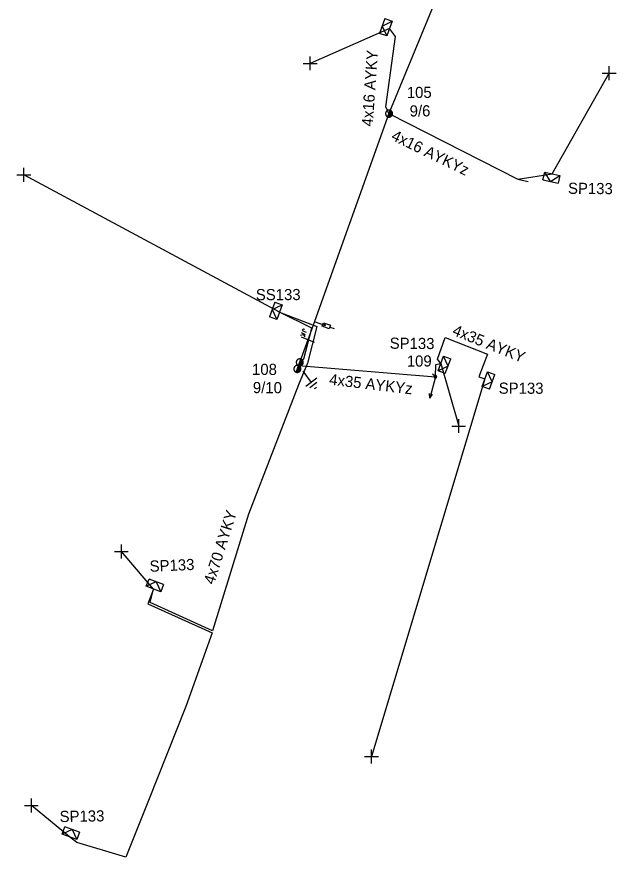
# Model space of a CAD drawing. Extents: x -748492 to -735633, y -1146251 to -1139940.
# Drawn here: x -740373.9 to -740320.2, y -1142310.5 to -1142235.2 of the extents above; entities that cross this region are included whole.
import ezdxf

# ---------------------------------------------------------------- set-up
doc = ezdxf.new("R2010")
doc.units = 0
for name, color, linetype in [('Vrstva 1', 7, 'Continuous'), ('Vrstva 12', 7, 'Continuous'), ('Vrstva 13', 7, 'Continuous'), ('Vrstva 14', 7, 'Continuous'), ('Vrstva 15', 7, 'Continuous'), ('Vrstva 16', 7, 'Continuous'), ('Vrstva 18', 7, 'Continuous'), ('Vrstva 2', 7, 'Continuous'), ('Vrstva 31', 7, 'Continuous'), ('Vrstva 33', 7, 'Continuous'), ('Vrstva 34', 7, 'Continuous'), ('Vrstva 5', 7, 'Continuous'), ('Vrstva 52', 7, 'Continuous'), ('Vrstva 53', 7, 'Continuous'), ('Vrstva 54', 7, 'Continuous'), ('Vrstva 55', 7, 'Continuous'), ('Vrstva 59', 7, 'Continuous'), ('Vrstva 6', 7, 'Continuous'), ('Vrstva 9', 7, 'Continuous')]:
    doc.layers.add(name, color=color, linetype=linetype)

# ---------------------------------------------------------------- blocks, each defined once
blk = doc.blocks.new('NN440')
at = {"layer": 'Vrstva 2'}
for points in [[(0.63, 0), (0.63, 0.06), (0.62, 0.13), (0.6, 0.19), (0.58, 0.25), (0.55, 0.31), (0.51, 0.37), (0.47, 0.42), (0.42, 0.46), (0.37, 0.51), (0.32, 0.54), (0.26, 0.57), (0.2, 0.59), (0.13, 0.61), (0.07, 0.62), (0, 0.63), (-0.06, 0.62), (-0.13, 0.61), (-0.19, 0.59), (-0.26, 0.57), (-0.31, 0.54), (-0.37, 0.51), (-0.42, 0.46), (-0.47, 0.42), (-0.51, 0.37), (-0.54, 0.31), (-0.57, 0.25), (-0.6, 0.19), (-0.62, 0.13), (-0.63, 0.06), (-0.63, 0), (-0.63, -0.07), (-0.62, -0.14), (-0.6, -0.2), (-0.57, -0.26), (-0.54, -0.32), (-0.51, -0.37), (-0.47, -0.43), (-0.42, -0.47), (-0.37, -0.51), (-0.31, -0.55), (-0.26, -0.58), (-0.19, -0.6), (-0.13, -0.62), (-0.06, -0.63), (0, -0.63), (0.07, -0.63), (0.13, -0.62), (0.2, -0.6), (0.26, -0.58), (0.32, -0.55), (0.37, -0.51), (0.42, -0.47), (0.47, -0.43), (0.51, -0.37), (0.55, -0.32), (0.58, -0.26), (0.6, -0.2), (0.62, -0.14), (0.63, -0.07), (0.63, 0)], [(-0.63, 0), (0.63, 0)], [(-0.6, -0.18), (0.57, -0.18)], [(-0.51, -0.32), (0.5, -0.32)], [(-0.37, -0.47), (0.35, -0.47)]]:
    blk.add_lwpolyline(points, dxfattribs=at)
blk = doc.blocks.new('NN450')
at = {"layer": 'Vrstva 2'}
for points in [[(0, 0), (0, 0.07), (-0.01, 0.13), (-0.03, 0.19), (-0.05, 0.25), (-0.08, 0.31), (-0.12, 0.37), (-0.16, 0.42), (-0.21, 0.46), (-0.26, 0.51), (-0.31, 0.54), (-0.37, 0.57), (-0.43, 0.59), (-0.5, 0.61), (-0.56, 0.62), (-0.63, 0.62), (-0.69, 0.62), (-0.75, 0.61), (-0.82, 0.59), (-0.88, 0.57), (-0.94, 0.54), (-0.99, 0.51), (-1.04, 0.46), (-1.09, 0.42), (-1.13, 0.37), (-1.17, 0.31), (-1.2, 0.25), (-1.22, 0.19), (-1.24, 0.13), (-1.25, 0.07), (-1.25, 0), (-1.25, -0.07), (-1.24, -0.13), (-1.22, -0.19), (-1.2, -0.25), (-1.17, -0.31), (-1.13, -0.37), (-1.09, -0.42), (-1.04, -0.46), (-0.99, -0.51), (-0.94, -0.54), (-0.88, -0.57), (-0.82, -0.59), (-0.75, -0.61), (-0.69, -0.62), (-0.62, -0.63), (-0.56, -0.62), (-0.5, -0.61), (-0.43, -0.59), (-0.37, -0.57), (-0.31, -0.54), (-0.26, -0.51), (-0.21, -0.46), (-0.16, -0.42), (-0.12, -0.37), (-0.08, -0.31), (-0.05, -0.25), (-0.03, -0.19), (-0.01, -0.13), (0, -0.07), (0, 0)], [(1.25, 0), (1.25, 0.07), (1.24, 0.13), (1.22, 0.19), (1.2, 0.25), (1.17, 0.31), (1.13, 0.37), (1.09, 0.42), (1.04, 0.46), (0.99, 0.51), (0.94, 0.54), (0.88, 0.57), (0.82, 0.59), (0.75, 0.61), (0.69, 0.62), (0.62, 0.62), (0.56, 0.62), (0.5, 0.61), (0.43, 0.59), (0.37, 0.57), (0.31, 0.54), (0.26, 0.51), (0.21, 0.46), (0.16, 0.42), (0.12, 0.37), (0.08, 0.31), (0.05, 0.25), (0.03, 0.19), (0.01, 0.13), (0, 0.07), (0, 0), (0, -0.07), (0.01, -0.13), (0.03, -0.19), (0.05, -0.25), (0.08, -0.31), (0.12, -0.37), (0.16, -0.42), (0.21, -0.46), (0.26, -0.51), (0.31, -0.54), (0.37, -0.57), (0.43, -0.59), (0.5, -0.61), (0.56, -0.62), (0.63, -0.63), (0.69, -0.62), (0.75, -0.61), (0.82, -0.59), (0.88, -0.57), (0.94, -0.54), (0.99, -0.51), (1.04, -0.46), (1.09, -0.42), (1.13, -0.37), (1.17, -0.31), (1.2, -0.25), (1.22, -0.19), (1.24, -0.13), (1.25, -0.07), (1.25, 0)], [(-1.25, 0), (1.25, 0)], [(-1.23, -0.16), (-0.02, -0.16)], [(-1.16, -0.32), (-0.09, -0.32)], [(-1.03, -0.47), (-0.22, -0.47)], [(0.02, -0.16), (1.23, -0.16)], [(0.09, -0.32), (1.16, -0.32)], [(0.22, -0.47), (1.03, -0.47)]]:
    blk.add_lwpolyline(points, dxfattribs=at)
blk = doc.blocks.new('NN560')
at = {"layer": 'Vrstva 2'}
for points in [[(1.999, -0.001), (1.59, 0.141)], [(0, -0.001), (1.999, -0.001)], [(1.999, -0.001), (1.59, -0.134)]]:
    blk.add_lwpolyline(points, dxfattribs=at)
blk = doc.blocks.new('NN840')
at = {"layer": 'Vrstva 15'}
for points in [[(0.003, 0.619), (0.003, -0.631)], [(-0.745, -0.71), (-0.745, -0.66)], [(-0.73, -0.764), (-0.745, -0.71)], [(-0.538, -0.71), (-0.558, -0.764)], [(-0.538, -0.385), (-0.538, -0.71)], [(-0.332, -0.385), (-0.332, -0.798)], [(-0.332, -0.641), (-0.125, -0.385)], [(-0.263, -0.557), (-0.091, -0.798)], [(-0.657, -0.798), (-0.73, -0.764)], [(-0.627, -0.798), (-0.657, -0.798)], [(-0.558, -0.764), (-0.627, -0.798)]]:
    blk.add_lwpolyline(points, dxfattribs=at)
blk = doc.blocks.new('NN800')
at = {"layer": 'Vrstva 1'}
for points in [[(-0.442, 0.442), (0.442, -0.442)], [(-0.442, -0.442), (0.442, 0.442)]]:
    blk.add_lwpolyline(points, dxfattribs=at)
blk = doc.blocks.new('NN820')
at = {"layer": 'Vrstva 13'}
for points in [[(-0.003, 0.004), (-0.003, -1.049)], [(-0.165, -0.813), (0.165, -0.813)], [(-0.165, -1.473), (-0.165, -0.813)], [(0.165, -1.473), (-0.165, -1.473)], [(-0.003, -1.049), (-0.062, -0.926)], [(-0.003, -1.049), (0.057, -0.926)], [(-0.003, -1.473), (-0.003, -1.871)], [(0.165, -0.813), (0.165, -1.473)]]:
    blk.add_lwpolyline(points, dxfattribs=at)
blk = doc.blocks.new('NN630')
at = {"layer": 'Vrstva 9'}
for points in [[(-0.003, -0.7), (-0.703, 0)], [(-0.703, -0.7), (-0.703, 0), (0.697, 0), (0.697, -0.7)], [(-0.703, -0.7), (0.697, -0.7)], [(-0.003, -0.7), (0.697, 0)]]:
    blk.add_lwpolyline(points, dxfattribs=at)
blk = doc.blocks.new('NN810')
at = {"layer": 'Vrstva 14'}
for points in [[(0.004, -0.64), (0.004, -1.89)], [(0.629, -1.89), (-0.621, -1.89)], [(0.388, -2.2), (-0.399, -2.2)], [(0.004, -2.515), (-0.124, -2.515)], [(0.137, -2.515), (0.004, -2.515)]]:
    blk.add_lwpolyline(points, dxfattribs=at)
blk = doc.blocks.new('NN500')
at = {"layer": 'Vrstva 2'}
for points in [[(0, -0.24), (0.02, -0.23), (0.05, -0.23), (0.07, -0.22), (0.09, -0.22), (0.12, -0.2), (0.14, -0.19), (0.16, -0.18), (0.17, -0.16), (0.19, -0.14), (0.2, -0.12), (0.21, -0.1), (0.22, -0.07), (0.23, -0.05), (0.23, -0.02), (0.23, 0), (0.23, 0.02), (0.23, 0.05), (0.22, 0.07), (0.21, 0.1), (0.2, 0.12), (0.19, 0.14), (0.17, 0.16), (0.16, 0.17), (0.14, 0.19), (0.12, 0.2), (0.09, 0.21), (0.07, 0.22), (0.05, 0.23), (0.02, 0.23), (0, 0.23), (-0.03, 0.23), (-0.05, 0.23), (-0.07, 0.22), (-0.1, 0.21), (-0.12, 0.2), (-0.14, 0.19), (-0.16, 0.17), (-0.18, 0.16), (-0.19, 0.14), (-0.2, 0.12), (-0.22, 0.1), (-0.22, 0.07), (-0.23, 0.05), (-0.23, 0.02), (-0.24, 0), (-0.23, -0.02), (-0.23, -0.05), (-0.22, -0.07), (-0.22, -0.1), (-0.2, -0.12), (-0.19, -0.14), (-0.18, -0.16), (-0.16, -0.18), (-0.14, -0.19), (-0.12, -0.2), (-0.1, -0.22), (-0.07, -0.22), (-0.05, -0.23), (-0.03, -0.23), (0, -0.24)], [(0, -0.24), (0.02, -0.23), (0.05, -0.23), (0.07, -0.22), (0.09, -0.22), (0.12, -0.2), (0.14, -0.19), (0.16, -0.18), (0.17, -0.16), (0.19, -0.14), (0.2, -0.12), (0.21, -0.1), (0.22, -0.07), (0.23, -0.05), (0.23, -0.02), (0.23, 0), (0.23, 0.02), (0.23, 0.05), (0.22, 0.07), (0.21, 0.1), (0.2, 0.12), (0.19, 0.14), (0.17, 0.16), (0.16, 0.17), (0.14, 0.19), (0.12, 0.2), (0.09, 0.21), (0.07, 0.22), (0.05, 0.23), (0.02, 0.23), (0, 0.23), (-0.03, 0.23), (-0.05, 0.23), (-0.07, 0.22), (-0.1, 0.21), (-0.12, 0.2), (-0.14, 0.19), (-0.16, 0.17), (-0.18, 0.16), (-0.19, 0.14), (-0.2, 0.12), (-0.22, 0.1), (-0.22, 0.07), (-0.23, 0.05), (-0.23, 0.02), (-0.24, 0), (-0.23, -0.02), (-0.23, -0.05), (-0.22, -0.07), (-0.22, -0.1), (-0.2, -0.12), (-0.19, -0.14), (-0.18, -0.16), (-0.16, -0.18), (-0.14, -0.19), (-0.12, -0.2), (-0.1, -0.22), (-0.07, -0.22), (-0.05, -0.23), (-0.03, -0.23), (0, -0.24)], [(0, -0.21), (0.02, -0.2), (0.04, -0.2), (0.06, -0.2), (0.08, -0.19), (0.1, -0.18), (0.12, -0.17), (0.14, -0.15), (0.15, -0.14), (0.16, -0.12), (0.18, -0.1), (0.19, -0.08), (0.19, -0.06), (0.2, -0.04), (0.2, -0.02), (0.2, 0), (0.2, 0.02), (0.2, 0.04), (0.19, 0.06), (0.19, 0.08), (0.18, 0.1), (0.16, 0.12), (0.15, 0.14), (0.14, 0.15), (0.12, 0.17), (0.1, 0.18), (0.08, 0.19), (0.06, 0.19), (0.04, 0.2), (0.02, 0.2), (0, 0.2), (-0.02, 0.2), (-0.04, 0.2), (-0.06, 0.19), (-0.08, 0.19), (-0.1, 0.18), (-0.12, 0.17), (-0.14, 0.15), (-0.15, 0.14), (-0.17, 0.12), (-0.18, 0.1), (-0.19, 0.08), (-0.2, 0.06), (-0.2, 0.04), (-0.21, 0.02), (-0.21, 0), (-0.21, -0.02), (-0.2, -0.04), (-0.2, -0.06), (-0.19, -0.08), (-0.18, -0.1), (-0.17, -0.12), (-0.15, -0.14), (-0.14, -0.15), (-0.12, -0.17), (-0.1, -0.18), (-0.08, -0.19), (-0.06, -0.2), (-0.04, -0.2), (-0.02, -0.2), (0, -0.21)], [(0, -0.18), (0.02, -0.18), (0.04, -0.17), (0.05, -0.17), (0.07, -0.16), (0.09, -0.15), (0.1, -0.14), (0.12, -0.13), (0.13, -0.12), (0.14, -0.1), (0.15, -0.09), (0.16, -0.07), (0.17, -0.05), (0.17, -0.04), (0.17, -0.02), (0.17, 0), (0.17, 0.02), (0.17, 0.04), (0.17, 0.05), (0.16, 0.07), (0.15, 0.09), (0.14, 0.1), (0.13, 0.12), (0.12, 0.13), (0.1, 0.14), (0.09, 0.15), (0.07, 0.16), (0.05, 0.17), (0.04, 0.17), (0.02, 0.17), (0, 0.18), (-0.02, 0.17), (-0.04, 0.17), (-0.06, 0.17), (-0.07, 0.16), (-0.09, 0.15), (-0.1, 0.14), (-0.12, 0.13), (-0.13, 0.12), (-0.14, 0.1), (-0.15, 0.09), (-0.16, 0.07), (-0.17, 0.05), (-0.17, 0.04), (-0.18, 0.02), (-0.18, 0), (-0.18, -0.02), (-0.17, -0.04), (-0.17, -0.05), (-0.16, -0.07), (-0.15, -0.09), (-0.14, -0.1), (-0.13, -0.12), (-0.12, -0.13), (-0.1, -0.14), (-0.09, -0.15), (-0.07, -0.16), (-0.06, -0.17), (-0.04, -0.17), (-0.02, -0.18), (0, -0.18)], [(0, -0.15), (0.01, -0.15), (0.03, -0.14), (0.04, -0.14), (0.06, -0.13), (0.07, -0.13), (0.08, -0.12), (0.1, -0.11), (0.11, -0.1), (0.12, -0.09), (0.13, -0.07), (0.13, -0.06), (0.14, -0.05), (0.14, -0.03), (0.14, -0.02), (0.14, 0), (0.14, 0.01), (0.14, 0.03), (0.14, 0.04), (0.13, 0.06), (0.13, 0.07), (0.12, 0.09), (0.11, 0.1), (0.1, 0.11), (0.08, 0.12), (0.07, 0.13), (0.06, 0.13), (0.04, 0.14), (0.03, 0.14), (0.01, 0.14), (0, 0.15), (-0.02, 0.14), (-0.03, 0.14), (-0.05, 0.14), (-0.06, 0.13), (-0.07, 0.13), (-0.09, 0.12), (-0.1, 0.11), (-0.11, 0.1), (-0.12, 0.09), (-0.13, 0.07), (-0.13, 0.06), (-0.14, 0.04), (-0.14, 0.03), (-0.15, 0.01), (-0.15, 0), (-0.15, -0.02), (-0.14, -0.03), (-0.14, -0.05), (-0.13, -0.06), (-0.13, -0.07), (-0.12, -0.09), (-0.11, -0.1), (-0.1, -0.11), (-0.09, -0.12), (-0.07, -0.13), (-0.06, -0.13), (-0.05, -0.14), (-0.03, -0.14), (-0.02, -0.15), (0, -0.15)], [(0, -0.12), (0.01, -0.12), (0.02, -0.11), (0.03, -0.11), (0.05, -0.11), (0.06, -0.1), (0.07, -0.09), (0.08, -0.09), (0.09, -0.08), (0.09, -0.07), (0.1, -0.06), (0.11, -0.05), (0.11, -0.04), (0.11, -0.02), (0.11, -0.01), (0.12, 0), (0.11, 0.01), (0.11, 0.02), (0.11, 0.04), (0.11, 0.05), (0.1, 0.06), (0.09, 0.07), (0.09, 0.08), (0.08, 0.09), (0.07, 0.09), (0.06, 0.1), (0.05, 0.11), (0.03, 0.11), (0.02, 0.11), (0.01, 0.12), (0, 0.12), (-0.01, 0.12), (-0.03, 0.11), (-0.04, 0.11), (-0.05, 0.11), (-0.06, 0.1), (-0.07, 0.09), (-0.08, 0.09), (-0.09, 0.08), (-0.1, 0.07), (-0.1, 0.06), (-0.11, 0.05), (-0.11, 0.04), (-0.12, 0.02), (-0.12, 0.01), (-0.12, 0), (-0.12, -0.01), (-0.12, -0.02), (-0.11, -0.04), (-0.11, -0.05), (-0.1, -0.06), (-0.1, -0.07), (-0.09, -0.08), (-0.08, -0.09), (-0.07, -0.09), (-0.06, -0.1), (-0.05, -0.11), (-0.04, -0.11), (-0.03, -0.11), (-0.01, -0.12), (0, -0.12)], [(0, -0.09), (0.01, -0.09), (0.02, -0.09), (0.03, -0.08), (0.03, -0.08), (0.04, -0.08), (0.05, -0.07), (0.06, -0.07), (0.06, -0.06), (0.07, -0.05), (0.07, -0.04), (0.08, -0.04), (0.08, -0.03), (0.08, -0.02), (0.09, -0.01), (0.09, 0), (0.09, 0.01), (0.08, 0.02), (0.08, 0.03), (0.08, 0.03), (0.07, 0.04), (0.07, 0.05), (0.06, 0.06), (0.06, 0.06), (0.05, 0.07), (0.04, 0.07), (0.03, 0.08), (0.03, 0.08), (0.02, 0.08), (0.01, 0.09), (0, 0.09), (-0.01, 0.09), (-0.02, 0.08), (-0.03, 0.08), (-0.04, 0.08), (-0.04, 0.07), (-0.05, 0.07), (-0.06, 0.06), (-0.07, 0.06), (-0.07, 0.05), (-0.08, 0.04), (-0.08, 0.03), (-0.08, 0.03), (-0.09, 0.02), (-0.09, 0.01), (-0.09, 0), (-0.09, -0.01), (-0.09, -0.02), (-0.08, -0.03), (-0.08, -0.04), (-0.08, -0.04), (-0.07, -0.05), (-0.07, -0.06), (-0.06, -0.07), (-0.05, -0.07), (-0.04, -0.08), (-0.04, -0.08), (-0.03, -0.08), (-0.02, -0.09), (-0.01, -0.09), (0, -0.09)], [(0, -0.06), (0, -0.06), (0.01, -0.06), (0.02, -0.05), (0.02, -0.05), (0.03, -0.05), (0.03, -0.05), (0.04, -0.04), (0.04, -0.04), (0.05, -0.03), (0.05, -0.03), (0.05, -0.02), (0.05, -0.02), (0.05, -0.01), (0.06, -0.01), (0.06, 0), (0.06, 0.01), (0.05, 0.01), (0.05, 0.02), (0.05, 0.02), (0.05, 0.03), (0.05, 0.03), (0.04, 0.04), (0.04, 0.04), (0.03, 0.05), (0.03, 0.05), (0.02, 0.05), (0.02, 0.05), (0.01, 0.06), (0, 0.06), (0, 0.06), (-0.01, 0.06), (-0.01, 0.06), (-0.02, 0.05), (-0.02, 0.05), (-0.03, 0.05), (-0.03, 0.05), (-0.04, 0.04), (-0.04, 0.04), (-0.05, 0.03), (-0.05, 0.03), (-0.05, 0.02), (-0.06, 0.02), (-0.06, 0.01), (-0.06, 0.01), (-0.06, 0), (-0.06, -0.01), (-0.06, -0.01), (-0.06, -0.02), (-0.05, -0.02), (-0.05, -0.03), (-0.05, -0.03), (-0.04, -0.04), (-0.04, -0.04), (-0.03, -0.05), (-0.03, -0.05), (-0.02, -0.05), (-0.02, -0.05), (-0.01, -0.06), (-0.01, -0.06), (0, -0.06)], [(0, -0.03), (0, -0.03), (0, -0.03), (0.01, -0.03), (0.01, -0.03), (0.01, -0.02), (0.02, -0.02), (0.02, -0.02), (0.02, -0.02), (0.02, -0.02), (0.02, -0.01), (0.02, -0.01), (0.03, -0.01), (0.03, -0.01), (0.03, 0), (0.03, 0), (0.03, 0), (0.03, 0.01), (0.03, 0.01), (0.02, 0.01), (0.02, 0.01), (0.02, 0.02), (0.02, 0.02), (0.02, 0.02), (0.02, 0.02), (0.01, 0.02), (0.01, 0.02), (0.01, 0.03), (0, 0.03), (0, 0.03), (0, 0.03), (0, 0.03), (-0.01, 0.03), (-0.01, 0.03), (-0.01, 0.02), (-0.02, 0.02), (-0.02, 0.02), (-0.02, 0.02), (-0.02, 0.02), (-0.02, 0.02), (-0.03, 0.01), (-0.03, 0.01), (-0.03, 0.01), (-0.03, 0.01), (-0.03, 0), (-0.03, 0), (-0.03, 0), (-0.03, -0.01), (-0.03, -0.01), (-0.03, -0.01), (-0.03, -0.01), (-0.02, -0.02), (-0.02, -0.02), (-0.02, -0.02), (-0.02, -0.02), (-0.02, -0.02), (-0.01, -0.03), (-0.01, -0.03), (-0.01, -0.03), (0, -0.03), (0, -0.03)], [(0.23, 0), (0.7, 0)]]:
    blk.add_lwpolyline(points, dxfattribs=at)
blk = doc.blocks.new('NN510')
at = {"layer": 'Vrstva 2'}
blk.add_lwpolyline([(0.001, 0.002), (0.001, 0.939)], dxfattribs=at)

msp = doc.modelspace()

# ---------------------------------------------------------------- linework, layer by layer
at = {"layer": 'Vrstva 1'}
msp.add_lwpolyline([(-740325.86, -1142208.25), (-740340.56, -1142243.88), (-740347.25, -1142262.515), (-740348.67, -1142266.47)], dxfattribs=at)
at = {"layer": 'Vrstva 5'}
for points in [[(-740348.67, -1142266.471), (-740348.19, -1142265.86), (-740347.48, -1142263.12), (-740350.38, -1142261.67), (-740347.04, -1142262.96), (-740347.86, -1142266.236), (-740348.682, -1142268.201), (-740353.17, -1142279.78), (-740356.374, -1142290.234), (-740361.965, -1142287.7), (-740361.67, -1142286.49), (-740362.171, -1142287.801), (-740356.428, -1142290.401), (-740358.77, -1142297.03), (-740362.12, -1142305.45), (-740364.17, -1142310.52), (-740368.54, -1142309.2), (-740369.22, -1142308.7)], [(-740336.4, -1142267.46), (-740336.372, -1142266.361), (-740335.919, -1142266.269), (-740336.207, -1142265.888), (-740335.509, -1142263.955), (-740331.726, -1142265.447), (-740332.507, -1142267.482), (-740331.972, -1142267.667)]]:
    msp.add_lwpolyline(points, dxfattribs=at)
at = {"layer": 'Vrstva 52'}
for points in [[(-740340.56, -1142243.88), (-740340.837, -1142243.292), (-740339.99, -1142236.98), (-740340.51, -1142236.27)], [(-740348.67, -1142266.47), (-740336.4, -1142267.46)]]:
    msp.add_lwpolyline(points, dxfattribs=at)
at = {"layer": 'Vrstva 54'}
msp.add_lwpolyline([(-740340.56, -1142243.88), (-740329, -1142249.771), (-740325.913, -1142249.286)], dxfattribs=at)
at = {"layer": 'Vrstva 59'}
for points in [[(-740340.51, -1142236.27), (-740347.63, -1142239.38)], [(-740325.913, -1142249.286), (-740320.81, -1142240.25)], [(-740350.38, -1142261.67), (-740373.31, -1142249.38)], [(-740335.919, -1142266.269), (-740334.31, -1142271.88)], [(-740331.972, -1142267.667), (-740342.13, -1142301.5)], [(-740361.67, -1142286.49), (-740364.56, -1142283.13)], [(-740369.22, -1142308.7), (-740372.63, -1142305.88)]]:
    msp.add_lwpolyline(points, dxfattribs=at)

# ---------------------------------------------------------------- block references
at = {"layer": 'Vrstva 13', "xscale": 0.5}
for name, p, yscale, rotation in [('NN440', (-740340.56, -1142243.881), 0.5, 64.98657225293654), ('NN450', (-740348.67, -1142266.469), 0.49999999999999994, 69.56400552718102), ('NN500', (-740336.4, -1142267.459), 0.5, 140.388547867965)]:
    msp.add_blockref(name, p, dxfattribs=dict(at, yscale=yscale, rotation=rotation))
at = {"layer": 'Vrstva 13'}
for name, p, rotation in [('NN510', (-740329, -1142249.77), -102.59943860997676), ('NN560', (-740336.4, -1142267.459), -103.97679165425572)]:
    msp.add_blockref(name, p, dxfattribs=dict(at, rotation=rotation))
at = {"layer": 'Vrstva 15', "rotation": 37.007652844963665}
msp.add_blockref('NN810', (-740348.67, -1142266.47), dxfattribs=at)
at = {"layer": 'Vrstva 16', "rotation": 70.25681701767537}
msp.add_blockref('NN820', (-740347.25, -1142262.515), dxfattribs=at)
at = {"layer": 'Vrstva 18', "rotation": -112.40058428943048}
msp.add_blockref('NN840', (-740347.806, -1142264.151), dxfattribs=at)
at = {"layer": 'Vrstva 31'}
for p, rotation in [((-740340.51, -1142236.27), -109.46649716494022), ((-740325.913, -1142249.286), -12.47994445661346), ((-740350.38, -1142261.67), -109.91650513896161), ((-740335.919, -1142266.269), 69.56400551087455), ((-740331.972, -1142267.667), 69.56400552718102), ((-740361.67, -1142286.49), 159.56400566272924), ((-740369.22, -1142308.701), 159.56400563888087)]:
    msp.add_blockref('NN630', p, dxfattribs=dict(at, rotation=rotation))
at = {"layer": 'Vrstva 34', "rotation": 45}
for p in [(-740347.63, -1142239.38), (-740320.81, -1142240.25), (-740373.31, -1142249.38), (-740334.31, -1142271.88), (-740364.56, -1142283.13), (-740342.13, -1142301.5), (-740372.63, -1142305.88)]:
    msp.add_blockref('NN800', p, dxfattribs=at)

# ---------------------------------------------------------------- texts
at = {"layer": 'Vrstva 12'}
for s, rotation, p in [('9/6', 0.384, (-740338.702, -1142244.145)), ('9/10', 359.75, (-740352.768, -1142268.934))]:
    msp.add_text(s, height=1, rotation=rotation, dxfattribs=at).set_placement(p)
at = {"layer": 'Vrstva 14'}
for s, rotation, p in [('105', 0.482, (-740338.957, -1142242.494)), ('109', 0.561, (-740338.956, -1142266.568)), ('108', 359.75, (-740352.844, -1142267.298))]:
    msp.add_text(s, height=1, rotation=rotation, dxfattribs=at).set_placement(p)
at = {"layer": 'Vrstva 33'}
for s, rotation, p in [('SP133', 359.502, (-740324.51, -1142251.073)), ('SS133', 0.176, (-740352.499, -1142260.61)), ('SP133', 359.499, (-740340.499, -1142264.956)), ('SP133', 359.831, (-740330.721, -1142268.986)), ('SP133', 2.467, (-740362, -1142284.947)), ('SP133', 0.902, (-740370.088, -1142307.373))]:
    msp.add_text(s, height=1, rotation=rotation, dxfattribs=at).set_placement(p)
at = {"layer": 'Vrstva 53'}
msp.add_text('4x35 AYKYz', height=1, rotation=353.312, dxfattribs=at).set_placement((-740345.961, -1142268.176))
at = {"layer": 'Vrstva 54'}
msp.add_text('4x16 AYKY', height=1, rotation=86.018, dxfattribs=at).set_placement((-740342.02, -1142245.06))
at = {"layer": 'Vrstva 55'}
msp.add_text('4x16 AYKYz', height=1, rotation=334.097, dxfattribs=at).set_placement((-740340.437, -1142246.198))
at = {"layer": 'Vrstva 6'}
for s, rotation, p in [('4x35 AYKY', 338.185, (-740334.954, -1142263.689)), ('4x70 AYKY', 72.408, (-740356.254, -1142286.14))]:
    msp.add_text(s, height=1, rotation=rotation, dxfattribs=at).set_placement(p)

doc.saveas('drawing.dxf')
